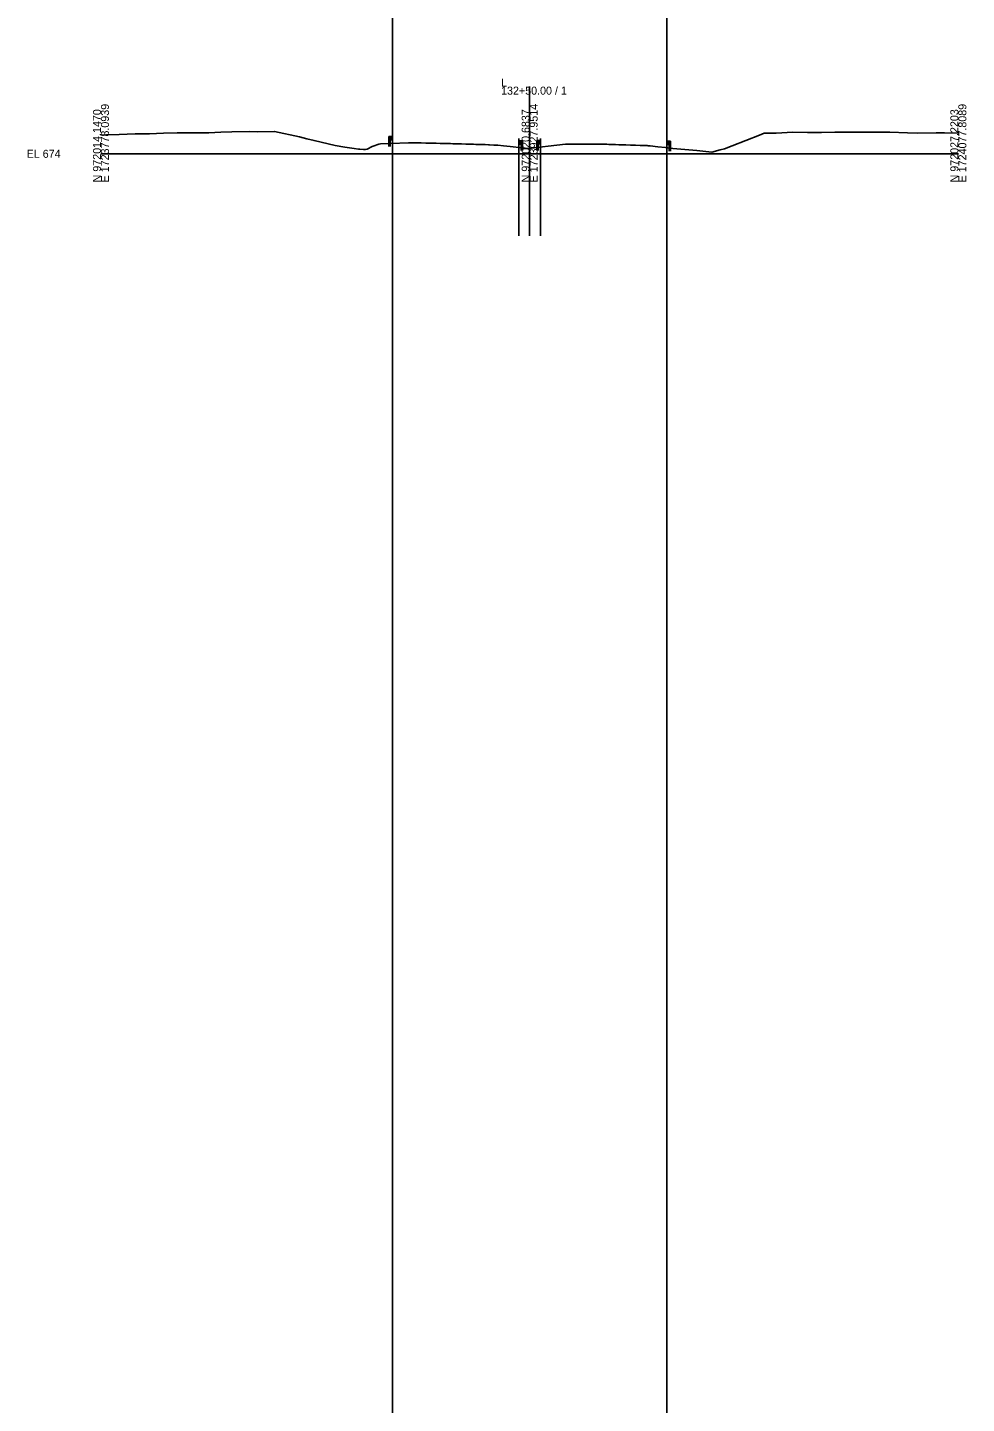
# Model space of a CAD drawing. Extents: x -26 to 303, y -29 to 15026.
# Drawn here: x -25.7 to 302.8, y 14062.6 to 14544.2 of the extents above; entities that cross this region are included whole.
import ezdxf

# ---------------------------------------------------------------- set-up
doc = ezdxf.new("R2010")
doc.units = 0
for name, color, linetype in [('Exist Cross Section Cell', 7, 'Continuous'), ('Exist XS Center Line Elevation Label', 7, 'Continuous'), ('Exist XS Ground Line', 7, 'Continuous'), ('Scratch_Level_0', 7, 'Continuous'), ('Typical Guardrail CELL', 7, 'Continuous')]:
    doc.layers.add(name, color=color, linetype=linetype)

msp = doc.modelspace()

# ---------------------------------------------------------------- linework, layer by layer
at = {"layer": 'Exist Cross Section Cell'}
for p, q in [((150, 14500), (150, 14523.5)), ((0, 14500), (150, 14500)), ((150, 14500), (300, 14500))]:
    msp.add_line(p, q, dxfattribs=at)
at = {"layer": 'Exist XS Ground Line'}
msp.add_lwpolyline([(0, 14506.54), (1.92, 14506.61), (6.35, 14506.77), (11.93, 14506.94), (17.04, 14506.97), (21.94, 14507.27), (26.63, 14507.32), (31.95, 14507.35), (37.75, 14507.29), (41.96, 14507.58), (45.81, 14507.65), (51.97, 14507.76), (54.63, 14507.74), (60.75, 14507.83), (69.49, 14505.93), (71.98, 14505.25), (74.58, 14504.6), (81.99, 14502.85), (85.31, 14502.31), (88.6, 14501.8), (90.14, 14501.57), (90.57, 14501.64), (91.86, 14501.5), (92.53, 14501.52), (93.1, 14501.67), (94.87, 14502.55), (95.26, 14502.69), (97.2, 14503.36), (97.76, 14503.48), (101.46, 14503.63), (107.65, 14503.85), (108.64, 14503.84), (110.3, 14503.83), (111.39, 14503.83), (112.06, 14503.8), (113.63, 14503.75), (114.64, 14503.73), (116.13, 14503.71), (117.24, 14503.68), (118.63, 14503.65), (119.9, 14503.61), (121.12, 14503.57), (122.27, 14503.55), (123.12, 14503.53), (123.61, 14503.52), (125.05, 14503.48), (126.1, 14503.45), (127.66, 14503.42), (128.6, 14503.4), (130.3, 14503.34), (131.11, 14503.31), (132.94, 14503.25), (133.62, 14503.23), (134.38, 14503.2), (135.63, 14503.15), (135.99, 14503.13), (137.51, 14503.08), (138.38, 14503.04), (138.84, 14503.03), (140.8, 14502.81), (143.22, 14502.56), (147.31, 14502.13), (149.77, 14501.87), (152.51, 14502.17), (156.46, 14502.62), (159.52, 14503.02), (162.52, 14503.38), (163.03, 14503.39), (163.82, 14503.4), (164.26, 14503.41), (165.46, 14503.4), (166.18, 14503.4), (167.86, 14503.39), (168.68, 14503.39), (169.56, 14503.39), (171.18, 14503.39), (172.67, 14503.37), (173.69, 14503.36), (174.8, 14503.35), (176.18, 14503.34), (176.67, 14503.33), (177.06, 14503.32), (177.68, 14503.3), (178.67, 14503.26), (180.01, 14503.22), (181.15, 14503.18), (182.21, 14503.16), (183.66, 14503.12), (185.24, 14503.06), (186.16, 14503.03), (186.99, 14503.01), (188.68, 14502.96), (189.34, 14502.93), (189.79, 14502.91), (191.16, 14502.85), (191.51, 14502.83), (192.19, 14502.79), (194.87, 14502.48), (197.51, 14502.19), (200.08, 14501.9), (208.48, 14501.13), (213.74, 14500.58), (216.71, 14501.36), (218.21, 14501.73), (220.83, 14502.78), (230.44, 14506.57), (232.07, 14507.24), (236.26, 14507.28), (242.14, 14507.57), (247.22, 14507.41), (252.15, 14507.48), (256.81, 14507.59), (262.16, 14507.6), (266.4, 14507.57), (272.16, 14507.54), (275.99, 14507.6), (282.17, 14507.35), (285.58, 14507.22), (292.18, 14507.33), (295.17, 14507.34), (300, 14507.21)], dxfattribs=at)
at = {"layer": 'Scratch_Level_0'}
for p, q in [((102, 15009.56), (102, -28.7)), ((198, 15009.56), (198, -28.7)), ((146.21, 14505.32), (146.21, 14471.3)), ((153.79, 14505.32), (153.79, 14471.3)), ((150, 14500), (150, 14471.3))]:
    msp.add_line(p, q, dxfattribs=at)
at = {"layer": 'Typical Guardrail CELL'}
for p, q in [((101.18, 14506.08), (100.68, 14506.08)), ((100.68, 14506.08), (100.68, 14503.6)), ((101.18, 14506.08), (101.18, 14503.6)), ((101.18, 14506.08), (101.68, 14506.08)), ((101.18, 14504.92), (101.68, 14504.92)), ((101.68, 14506.08), (101.68, 14504.92)), ((101.68, 14506.08), (101.97, 14505.88)), ((101.68, 14505.55), (101.97, 14505.75)), ((101.68, 14505.5), (101.68, 14505.55)), ((101.68, 14505.5), (101.68, 14505.45)), ((101.68, 14505.45), (101.97, 14505.25)), ((101.68, 14504.92), (101.97, 14505.12)), ((101.18, 14503.6), (100.68, 14503.6)), ((100.68, 14503.6), (100.68, 14502.59)), ((101.18, 14503.6), (101.18, 14502.59)), ((146.53, 14504.59), (146.24, 14504.39)), ((146.53, 14504.06), (146.24, 14504.26)), ((146.53, 14503.97), (146.24, 14503.76)), ((146.53, 14503.43), (146.24, 14503.64)), ((147.03, 14504.59), (146.53, 14504.59)), ((146.53, 14504.59), (146.53, 14503.43)), ((146.53, 14504.01), (146.53, 14504.06)), ((146.53, 14504.01), (146.53, 14503.97)), ((147.03, 14503.43), (146.53, 14503.43)), ((147.03, 14504.59), (147.03, 14502.11)), ((147.03, 14504.59), (147.53, 14504.59)), ((147.03, 14502.11), (147.53, 14502.11)), ((147.03, 14502.11), (147.03, 14501.1)), ((147.53, 14504.59), (147.53, 14502.11)), ((147.53, 14502.11), (147.53, 14501.1)), ((152.97, 14504.65), (152.47, 14504.65)), ((152.47, 14504.65), (152.47, 14502.16)), ((152.97, 14502.16), (152.47, 14502.16)), ((152.47, 14502.16), (152.47, 14501.16)), ((152.97, 14504.65), (152.97, 14502.16)), ((152.97, 14504.65), (153.47, 14504.65)), ((152.97, 14503.49), (153.47, 14503.49)), ((152.97, 14502.16), (152.97, 14501.16)), ((153.47, 14504.65), (153.47, 14503.49)), ((153.47, 14504.65), (153.76, 14504.45)), ((153.47, 14504.12), (153.76, 14504.32)), ((153.47, 14504.07), (153.47, 14504.12)), ((153.47, 14504.07), (153.47, 14504.02)), ((153.47, 14504.02), (153.76, 14503.82)), ((153.47, 14503.49), (153.76, 14503.69)), ((198.32, 14504.47), (198.03, 14504.26)), ((198.32, 14503.93), (198.03, 14504.14)), ((198.32, 14503.84), (198.03, 14503.64)), ((198.32, 14503.31), (198.03, 14503.51)), ((198.82, 14504.47), (198.32, 14504.47)), ((198.32, 14504.47), (198.32, 14503.31)), ((198.32, 14503.89), (198.32, 14503.93)), ((198.32, 14503.89), (198.32, 14503.84)), ((198.82, 14503.31), (198.32, 14503.31)), ((198.82, 14504.47), (198.82, 14501.98)), ((198.82, 14504.47), (199.32, 14504.47)), ((198.82, 14501.98), (199.32, 14501.98)), ((198.82, 14501.98), (198.82, 14500.97)), ((199.32, 14504.47), (199.32, 14501.98)), ((199.32, 14501.98), (199.32, 14500.97))]:
    msp.add_line(p, q, dxfattribs=at)
for centre, start, end in [((101.92, 14505.81), 304.9888, 54.997), ((101.92, 14505.19), 304.9634, 54.9941), ((146.29, 14504.33), 125.003, 235.0112), ((146.29, 14503.7), 125.0059, 235.0366), ((153.71, 14504.38), 304.9888, 54.997), ((153.71, 14503.76), 304.9634, 54.9941), ((198.08, 14504.2), 125.003, 235.0112), ((198.08, 14503.57), 125.0059, 235.0366)]:
    msp.add_arc(centre, 0.0776, start, end, dxfattribs=at)

# ---------------------------------------------------------------- texts
at = {"layer": 'Exist Cross Section Cell'}
for s, p in [('L', (140, 14523.5)), ('132+50.00 / 1', (140, 14520.7)), ('EL 674', (-26, 14498.6))]:
    msp.add_text(s, height=2.8, dxfattribs=at).set_placement(p)
for s, p in [('N 972014.1470', (0, 14490)), ('E 1723778.0939', (2.8, 14490)), ('N 972020.6837', (150, 14490)), ('E 1723927.9514', (152.8, 14490)), ('N 972027.2203', (300, 14490)), ('E 1724077.8089', (302.8, 14490))]:
    msp.add_text(s, height=2.8, rotation=90, dxfattribs=at).set_placement(p)
at = {"layer": 'Exist XS Center Line Elevation Label'}
msp.add_text('675.90', height=0.18, dxfattribs=at).set_placement((149.61, 14501.41))

doc.saveas('drawing.dxf')
